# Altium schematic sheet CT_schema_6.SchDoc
size 372 x 245 mm
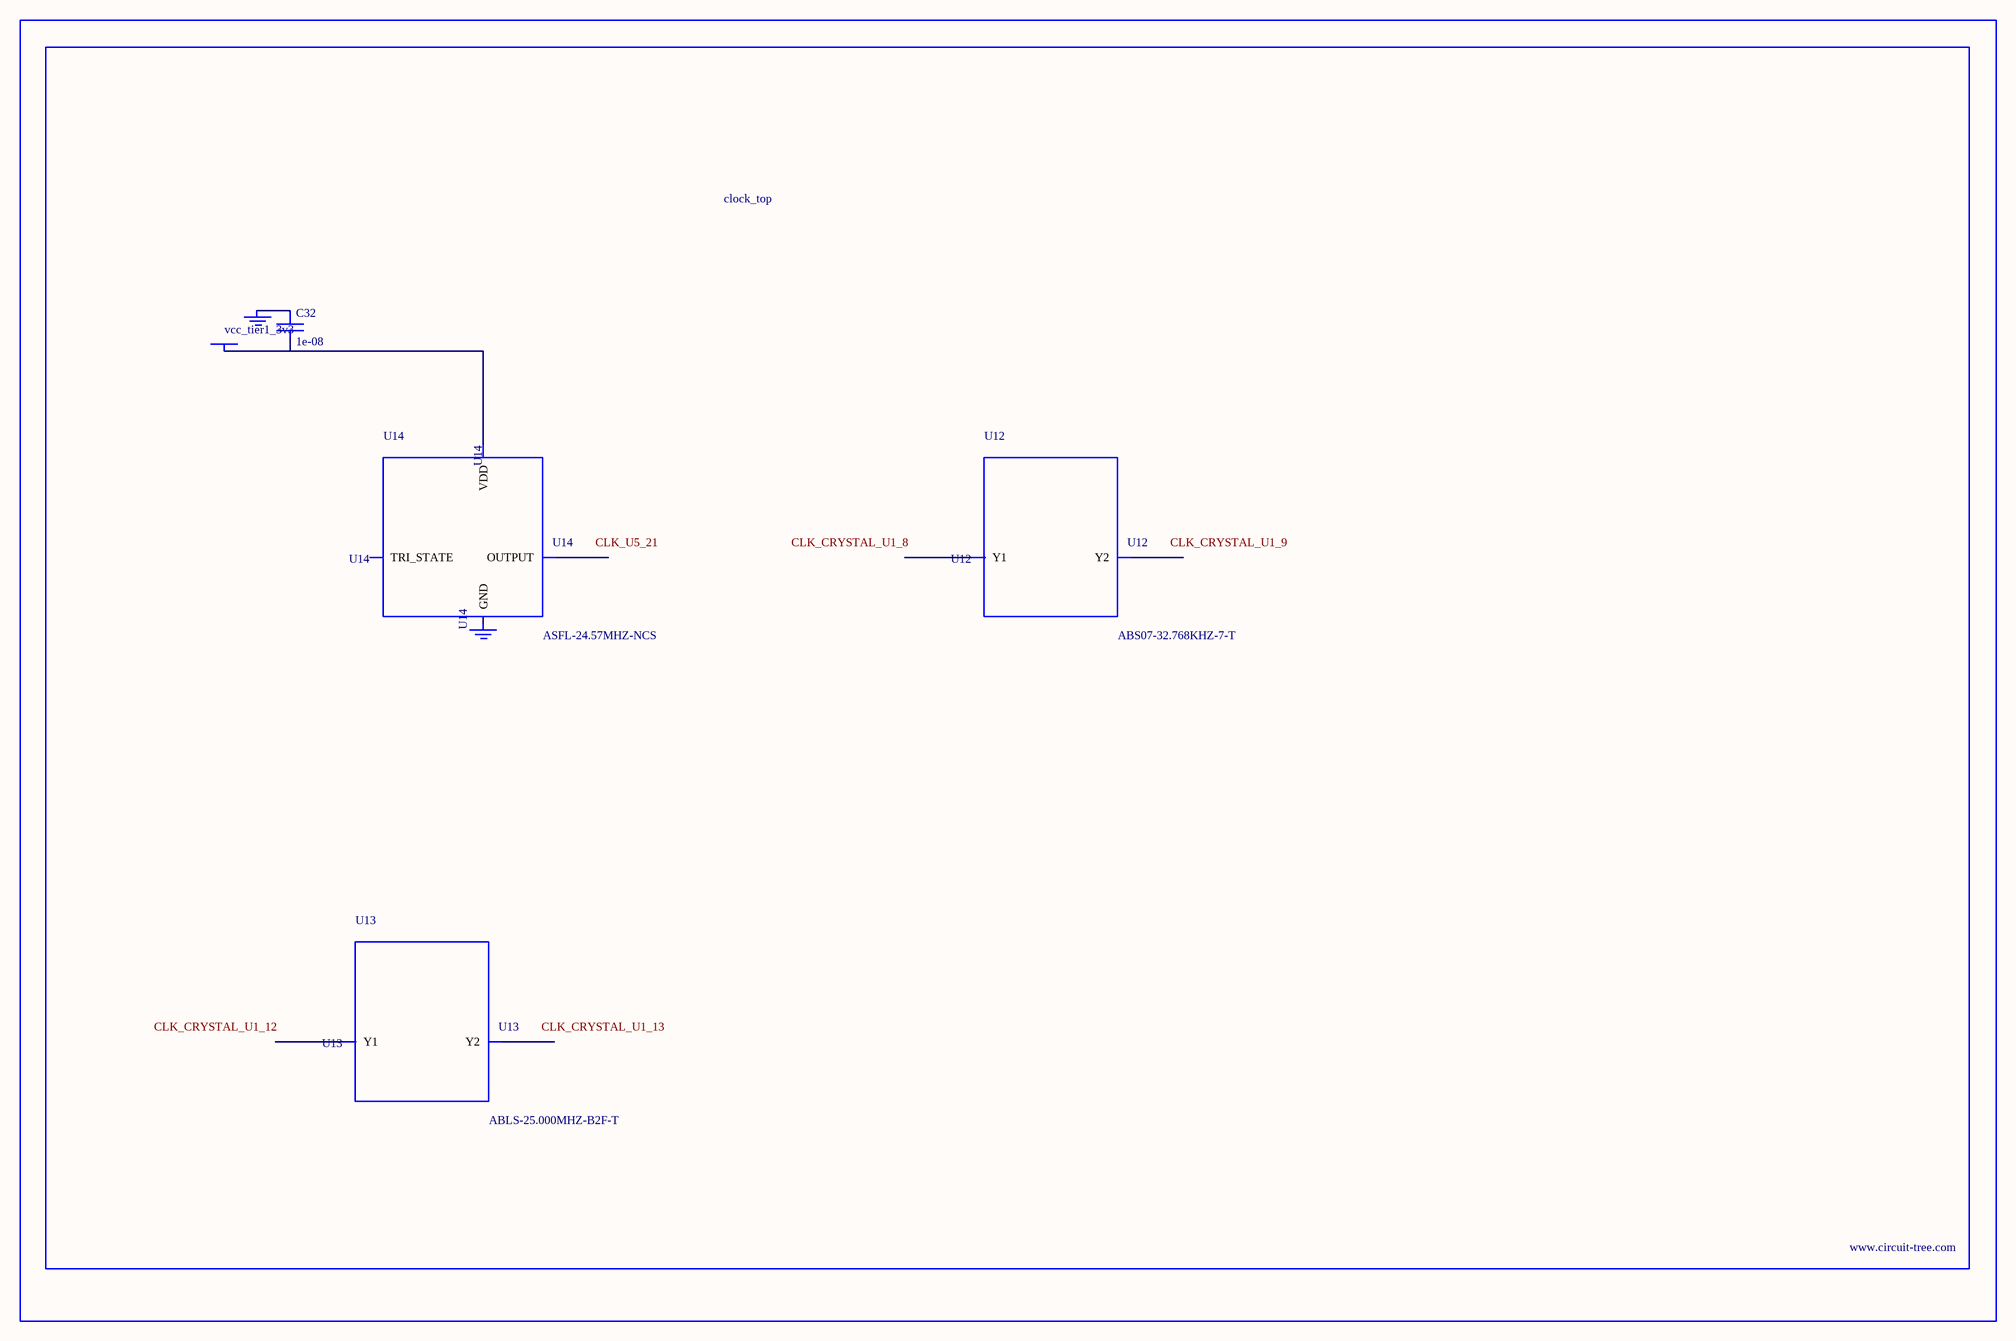
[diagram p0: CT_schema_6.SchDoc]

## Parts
BORDER5  (no value)
C32  1e-08  [C0402]
GND_INSTANCE_5_0  (no value)
GND_INSTANCE_5_1  (no value)
POWER_INSTANCE_5_0  vcc_tier1_3v3
U12  ABS07-32.768KHZ-7-T  [ABS07-32.768KHZ-7-T]
U13  ABLS-25.000MHZ-B2F-T  [ABLS-25.000MHZ-B2F-T]
U14  ASFL-24.57MHZ-NCS  [ASFL1]

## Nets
NetC32_1: C32.1 GND_INSTANCE_5_0.0(GND)
NetC32_2: C32.2 POWER_INSTANCE_5_0.0(PWR) U14.4(VDD)

Not connected (* = marked no-connect by the designer): GND_INSTANCE_5_1 0(GND); U12 1(Y1) 2(Y2); U13 1(Y1) 2(Y2); U14 1(TRI_STATE) 2(GND) 3(OUTPUT)

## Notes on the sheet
- Labels drawn without touching a wire or pin: CLK_CRYSTAL_U1_8, CLK_CRYSTAL_U1_9, CLK_CRYSTAL_U1_12, CLK_CRYSTAL_U1_13, CLK_U5_21

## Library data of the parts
BORDER5 = BORDER_PAGE5
C32 = C0402C103K3RAC
GND_INSTANCE_5_0 GND_INSTANCE_5_1 = GND
POWER_INSTANCE_5_0 = PWR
